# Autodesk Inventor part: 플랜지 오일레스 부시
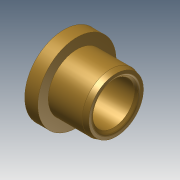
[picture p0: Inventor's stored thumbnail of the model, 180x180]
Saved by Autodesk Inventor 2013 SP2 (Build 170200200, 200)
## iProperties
Created: 2025-04
Part Number: 플랜지 오일레스 부시
Material: Generic
Document SubType Name: Modeling
Designer: i
Density: 1 g/cm^3
Author: i
변환 표준: STEP AP214IS
전처리기: Build: 200, Release: 2013 SP2 Update 6 - Date: Thu 07/17/2014
전송 단위: 밀리미터
불확실성: 0.01
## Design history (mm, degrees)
node "플랜지 오일레스 부시1"
node "솔리드1"
node "기준1"
